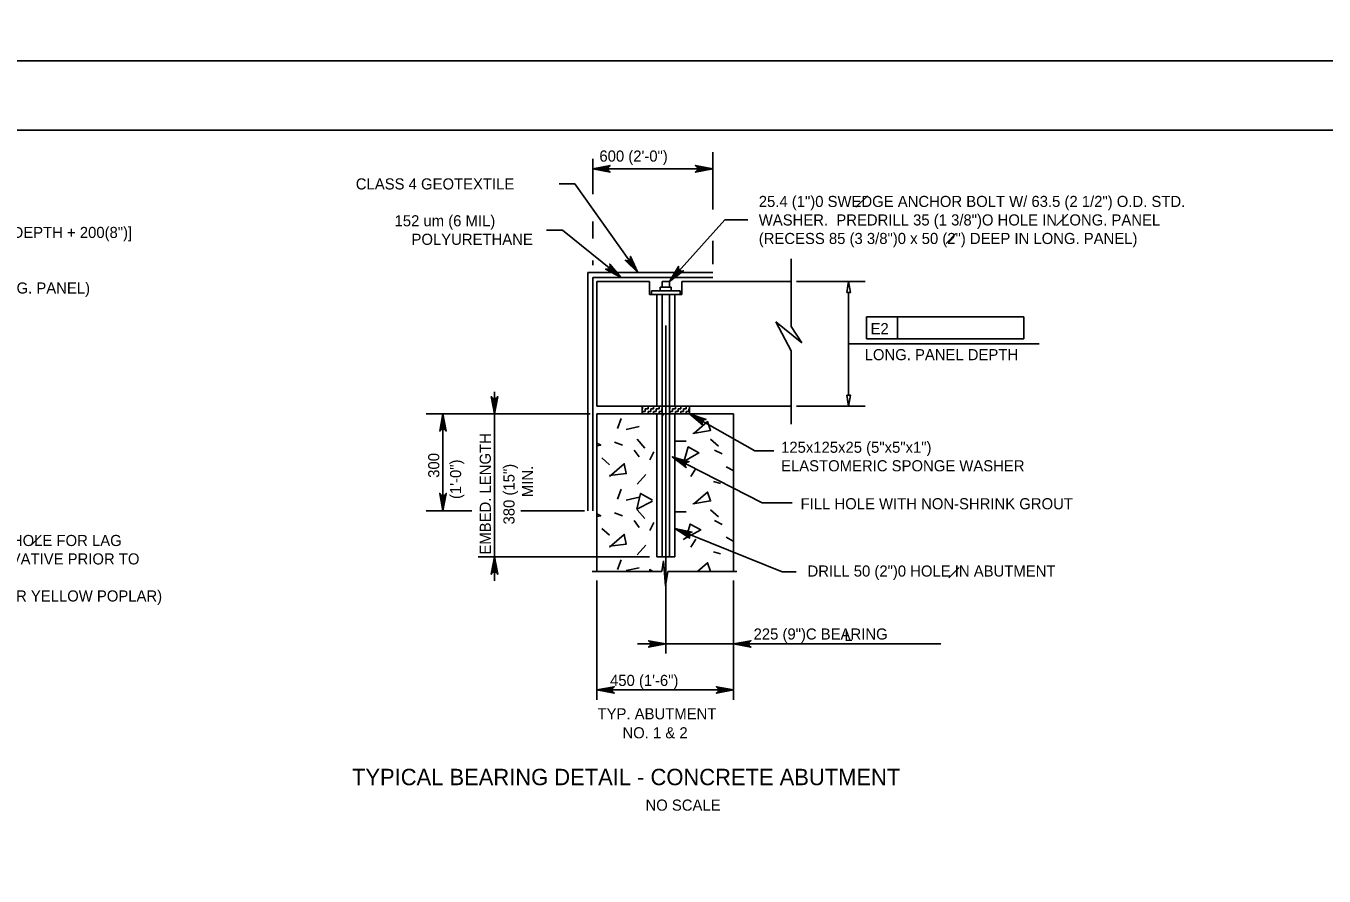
# Model space of a CAD drawing. Extents: x -8 to 75, y -110 to 0.
# Drawn here: x 45.04 to 59.07, y -74.81 to -65.62 of the extents above; entities that cross this region are included whole.
import ezdxf

# ---------------------------------------------------------------- set-up
doc = ezdxf.new("R2010")
doc.units = 0
for name, color, linetype in [('1', 7, 'Continuous'), ('2', 7, 'Continuous'), ('3', 7, 'Continuous'), ('4', 7, 'Continuous'), ('63', 7, 'Continuous')]:
    doc.layers.add(name, color=color, linetype=linetype)

msp = doc.modelspace()

# ---------------------------------------------------------------- linework, layer by layer
at = {"layer": '1'}
msp.add_lwpolyline([(35.75, -87.25), (67.25, -87.25), (67.25, -66.75), (35.75, -66.75)], close=True, dxfattribs=at)
at = {"layer": '2'}
for p, q in [((51.115, -68.286), (51.115, -70.86)), ((51.115, -68.286), (52.463, -68.286)), ((51.169, -68.34), (51.169, -70.86)), ((51.169, -68.34), (52.463, -68.34)), ((51.213, -68.384), (51.213, -69.731)), ((51.213, -68.384), (51.782, -68.384)), ((51.782, -68.526), (51.782, -68.384)), ((51.917, -68.384), (51.996, -68.384)), ((51.917, -68.384), (51.917, -68.447)), ((51.996, -68.384), (51.996, -68.447)), ((52.13, -68.526), (52.13, -68.384)), ((52.13, -68.384), (53.306, -68.384)), ((51.782, -68.526), (52.13, -68.526)), ((51.803, -68.486), (52.11, -68.486)), ((51.803, -68.526), (51.803, -68.486)), ((51.858, -69.731), (51.858, -68.526)), ((51.897, -68.486), (51.897, -68.447)), ((51.897, -68.447), (52.015, -68.447)), ((51.917, -68.526), (51.917, -71.36)), ((51.996, -68.526), (51.996, -71.36)), ((52.015, -68.486), (52.015, -68.447)), ((52.055, -69.731), (52.055, -68.526)), ((52.11, -68.526), (52.11, -68.486)), ((51.956, -68.599), (51.956, -68.599)), ((51.213, -69.731), (53.306, -69.731)), ((51.213, -69.814), (52.689, -69.814)), ((51.213, -69.814), (51.213, -71.516)), ((51.7, -69.731), (51.7, -69.814)), ((51.7, -69.76), (51.706, -69.76)), ((51.706, -69.76), (51.706, -69.731)), ((51.706, -69.79), (51.735, -69.79)), ((51.706, -69.814), (51.706, -69.79)), ((51.735, -69.76), (51.765, -69.76)), ((51.735, -69.79), (51.735, -69.76)), ((51.765, -69.76), (51.765, -69.731)), ((51.765, -69.79), (51.794, -69.79)), ((51.765, -69.814), (51.765, -69.79)), ((51.794, -69.76), (51.824, -69.76)), ((51.794, -69.79), (51.794, -69.76)), ((51.824, -69.76), (51.824, -69.731)), ((51.824, -69.79), (51.853, -69.79)), ((51.824, -69.814), (51.824, -69.79)), ((51.853, -69.76), (51.883, -69.76)), ((51.853, -69.79), (51.853, -69.76)), ((51.858, -71.36), (51.858, -69.814)), ((51.883, -69.76), (51.883, -69.731)), ((51.883, -69.79), (51.912, -69.79)), ((51.883, -69.814), (51.883, -69.79)), ((51.912, -69.76), (51.917, -69.76)), ((51.912, -69.79), (51.912, -69.76)), ((51.996, -69.76), (52.001, -69.76)), ((52.001, -69.76), (52.001, -69.731)), ((52.001, -69.79), (52.03, -69.79)), ((52.001, -69.814), (52.001, -69.79)), ((52.03, -69.76), (52.06, -69.76)), ((52.03, -69.79), (52.03, -69.76)), ((52.055, -71.36), (52.055, -69.814)), ((52.06, -69.76), (52.06, -69.731)), ((52.06, -69.79), (52.089, -69.79)), ((52.06, -69.814), (52.06, -69.79)), ((52.089, -69.76), (52.119, -69.76)), ((52.089, -69.79), (52.089, -69.76)), ((52.119, -69.76), (52.119, -69.731)), ((52.119, -69.79), (52.148, -69.79)), ((52.119, -69.814), (52.119, -69.79)), ((52.148, -69.76), (52.178, -69.76)), ((52.148, -69.79), (52.148, -69.76)), ((52.178, -69.76), (52.178, -69.731)), ((52.178, -69.79), (52.207, -69.79)), ((52.178, -69.814), (52.178, -69.79)), ((52.207, -69.76), (52.212, -69.76)), ((52.207, -69.79), (52.207, -69.76)), ((52.212, -69.731), (52.212, -69.814)), ((52.689, -69.814), (52.689, -71.516)), ((51.858, -71.36), (52.055, -71.36)), ((51.16, -71.516), (51.912, -71.516)), ((51.912, -71.516), (51.931, -71.4)), ((51.931, -71.4), (51.954, -71.67)), ((51.954, -71.67), (51.979, -71.516)), ((51.979, -71.516), (52.725, -71.516))]:
    msp.add_line(p, q, dxfattribs=at)
at = {"layer": '3'}
for p, q in [((52.463, -67.607), (52.463, -66.988)), ((51.169, -67.442), (51.169, -67.061)), ((52.463, -67.168), (51.169, -67.168)), ((50.972, -67.331), (50.803, -67.331)), ((54.011, -67.582), (54.135, -67.459)), ((51.169, -67.919), (51.169, -67.736)), ((52.593, -67.72), (52.844, -67.72)), ((56.178, -67.78), (56.302, -67.656)), ((50.839, -67.829), (50.666, -67.829)), ((54.985, -67.974), (55.092, -67.868)), ((52.464, -68.197), (52.464, -67.947)), ((51.169, -68.207), (51.169, -68.157)), ((53.311, -68.141), (53.311, -68.872)), ((53.369, -68.384), (54.112, -68.384)), ((53.932, -68.504), (53.932, -69.611)), ((51.956, -68.859), (51.956, -72.402)), ((53.144, -68.82), (53.311, -69.132)), ((53.425, -69.049), (53.144, -68.82)), ((54.125, -68.768), (55.826, -68.768)), ((54.125, -69.004), (54.125, -68.768)), ((54.46, -69.004), (54.46, -68.768)), ((55.826, -68.768), (55.826, -69.004)), ((53.311, -68.872), (53.425, -69.049)), ((55.826, -69.004), (54.125, -69.004)), ((53.311, -69.132), (53.311, -69.924)), ((53.932, -69.057), (55.992, -69.057)), ((50.105, -69.814), (50.105, -69.578)), ((50.714, -69.814), (49.369, -69.814)), ((49.549, -69.814), (49.549, -70.86)), ((51.14, -69.814), (49.928, -69.814)), ((50.105, -69.814), (50.105, -71.36)), ((51.931, -69.814), (51.921, -69.834)), ((53.369, -69.731), (54.112, -69.731)), ((51.476, -69.866), (51.434, -69.972)), ((51.667, -69.951), (51.529, -69.982)), ((51.402, -70.12), (51.487, -70.152)), ((51.646, -70.088), (51.731, -70.184)), ((52.059, -70.109), (52.175, -70.109)), ((52.44, -70.088), (52.525, -70.162)), ((51.614, -70.205), (51.667, -70.279)), ((51.826, -70.226), (51.783, -70.311)), ((52.482, -70.205), (52.567, -70.247)), ((52.917, -70.212), (53.124, -70.212)), ((51.265, -70.289), (51.349, -70.364)), ((52.228, -70.491), (52.281, -70.406)), ((52.61, -70.385), (52.684, -70.427)), ((51.741, -70.47), (51.646, -70.575)), ((52.472, -70.544), (52.546, -70.565)), ((51.476, -70.628), (51.434, -70.734)), ((51.667, -70.713), (51.529, -70.745)), ((52.998, -70.777), (53.323, -70.777)), ((49.861, -70.86), (49.369, -70.86)), ((51.079, -70.86), (50.391, -70.86)), ((51.402, -70.883), (51.487, -70.914)), ((51.614, -70.967), (51.667, -71.041)), ((51.646, -70.851), (51.731, -70.946)), ((52.059, -70.872), (52.175, -70.872)), ((52.44, -70.851), (52.525, -70.925)), ((52.482, -70.967), (52.567, -71.01)), ((51.265, -71.052), (51.349, -71.126)), ((51.826, -70.988), (51.783, -71.073)), ((45.101, -71.232), (45.209, -71.124)), ((51.741, -71.232), (51.646, -71.338)), ((52.228, -71.253), (52.281, -71.168)), ((52.61, -71.147), (52.684, -71.19)), ((51.781, -71.36), (49.928, -71.36)), ((50.105, -71.36), (50.105, -71.596)), ((52.472, -71.306), (52.546, -71.327)), ((51.476, -71.391), (51.434, -71.497)), ((51.667, -71.476), (51.529, -71.507)), ((53.215, -71.52), (53.366, -71.52)), ((55.014, -71.585), (55.127, -71.473)), ((50.105, -71.596), (50.105, -71.618)), ((51.213, -71.615), (51.213, -72.904)), ((52.689, -71.615), (52.689, -72.904)), ((52.689, -72.159), (52.689, -72.354)), ((51.956, -72.299), (51.65, -72.299)), ((51.916, -72.299), (52.925, -72.299)), ((52.925, -72.299), (54.929, -72.299)), ((52.689, -72.796), (51.213, -72.796))]:
    msp.add_line(p, q, dxfattribs=at)
for points in [[(51.169, -67.168), (51.355, -67.133), (51.341, -67.143), (51.334, -67.156), (51.331, -67.168), (51.334, -67.181), (51.341, -67.193), (51.355, -67.203), (51.169, -67.168), (51.341, -67.193), (51.334, -67.181), (51.169, -67.168), (51.331, -67.168), (51.334, -67.156), (51.169, -67.168), (51.341, -67.143)], [(52.463, -67.168), (52.277, -67.203), (52.291, -67.193), (52.299, -67.181), (52.301, -67.168), (52.299, -67.156), (52.291, -67.143), (52.277, -67.133), (52.463, -67.168), (52.291, -67.143), (52.299, -67.156), (52.463, -67.168), (52.301, -67.168), (52.299, -67.181), (52.463, -67.168), (52.291, -67.193)], [(51.655, -68.286), (50.972, -67.331)], [(51.996, -68.384), (52.593, -67.72)], [(51.473, -68.34), (50.839, -67.829)], [(51.655, -68.286), (51.519, -68.155), (51.535, -68.161), (51.549, -68.159), (51.561, -68.154), (51.57, -68.145), (51.576, -68.132), (51.575, -68.114), (51.655, -68.286), (51.576, -68.132), (51.57, -68.145), (51.655, -68.286), (51.561, -68.154), (51.549, -68.159), (51.655, -68.286), (51.535, -68.161)], [(51.473, -68.34), (51.306, -68.251), (51.324, -68.252), (51.337, -68.247), (51.347, -68.238), (51.353, -68.227), (51.355, -68.213), (51.35, -68.196), (51.473, -68.34), (51.355, -68.213), (51.353, -68.227), (51.473, -68.34), (51.347, -68.238), (51.337, -68.247), (51.473, -68.34), (51.324, -68.252)], [(51.996, -68.384), (52.094, -68.222), (52.092, -68.239), (52.096, -68.253), (52.104, -68.263), (52.115, -68.27), (52.129, -68.273), (52.146, -68.269), (51.996, -68.384), (52.129, -68.273), (52.115, -68.27), (51.996, -68.384), (52.104, -68.263), (52.096, -68.253), (51.996, -68.384), (52.092, -68.239)], [(50.105, -69.814), (50.07, -69.627), (50.08, -69.642), (50.092, -69.649), (50.105, -69.651), (50.117, -69.649), (50.13, -69.642), (50.14, -69.627), (50.105, -69.814), (50.13, -69.642), (50.117, -69.649), (50.105, -69.814), (50.105, -69.651), (50.092, -69.649), (50.105, -69.814), (50.08, -69.642)], [(49.549, -69.814), (49.584, -70), (49.574, -69.986), (49.562, -69.978), (49.549, -69.976), (49.537, -69.978), (49.524, -69.986), (49.514, -70), (49.549, -69.814), (49.524, -69.986), (49.537, -69.978), (49.549, -69.814), (49.549, -69.976), (49.562, -69.978), (49.549, -69.814), (49.574, -69.986)], [(52.212, -69.814), (52.917, -70.212)], [(52.212, -69.814), (52.392, -69.875), (52.374, -69.877), (52.362, -69.884), (52.354, -69.894), (52.349, -69.906), (52.35, -69.92), (52.357, -69.936), (52.212, -69.814), (52.35, -69.92), (52.349, -69.906), (52.212, -69.814), (52.354, -69.894), (52.362, -69.884), (52.212, -69.814), (52.374, -69.877)], [(52.249, -70.025), (52.44, -69.993), (52.408, -69.898), (52.26, -70.025)], [(51.213, -70.16), (51.254, -70.152), (51.213, -70.131)], [(52.125, -70.342), (52.315, -70.236), (52.199, -70.172), (52.156, -70.321)], [(51.349, -70.48), (51.529, -70.459), (51.508, -70.353), (51.349, -70.491)], [(52.026, -70.278), (52.998, -70.776)], [(52.026, -70.278), (52.208, -70.332), (52.19, -70.334), (52.178, -70.342), (52.17, -70.352), (52.167, -70.364), (52.167, -70.379), (52.176, -70.394), (52.026, -70.278), (52.167, -70.379), (52.167, -70.364), (52.026, -70.278), (52.17, -70.352), (52.178, -70.342), (52.026, -70.278), (52.19, -70.334)], [(49.549, -70.86), (49.514, -70.674), (49.524, -70.688), (49.537, -70.696), (49.549, -70.698), (49.562, -70.696), (49.574, -70.688), (49.584, -70.674), (49.549, -70.86), (49.574, -70.688), (49.562, -70.696), (49.549, -70.86), (49.549, -70.698), (49.537, -70.696), (49.549, -70.86), (49.524, -70.688)], [(51.811, -70.758), (51.642, -70.842), (51.684, -70.673), (51.811, -70.747)], [(52.249, -70.787), (52.44, -70.755), (52.408, -70.66), (52.26, -70.787)], [(51.213, -70.922), (51.254, -70.914), (51.213, -70.894)], [(52.055, -71.054), (53.215, -71.52)], [(52.055, -71.054), (52.241, -71.091), (52.224, -71.095), (52.212, -71.104), (52.206, -71.115), (52.203, -71.127), (52.205, -71.142), (52.215, -71.156), (52.055, -71.054), (52.205, -71.142), (52.203, -71.127), (52.055, -71.054), (52.206, -71.115), (52.212, -71.104), (52.055, -71.054), (52.224, -71.095)], [(52.144, -71.173), (52.334, -71.067), (52.218, -71.004), (52.176, -71.152)], [(51.349, -71.243), (51.529, -71.221), (51.508, -71.116), (51.349, -71.253)], [(50.105, -71.36), (50.14, -71.546), (50.13, -71.532), (50.117, -71.524), (50.105, -71.522), (50.092, -71.524), (50.08, -71.532), (50.07, -71.546), (50.105, -71.36), (50.08, -71.532), (50.092, -71.524), (50.105, -71.36), (50.105, -71.522), (50.117, -71.524), (50.105, -71.36), (50.13, -71.532)], [(51.779, -71.516), (51.783, -71.497), (51.816, -71.516)], [(52.439, -71.516), (52.408, -71.423), (52.3, -71.516)], [(51.956, -72.299), (51.77, -72.334), (51.784, -72.324), (51.792, -72.312), (51.794, -72.299), (51.792, -72.287), (51.784, -72.274), (51.77, -72.264), (51.956, -72.299), (51.784, -72.274), (51.792, -72.287), (51.956, -72.299), (51.794, -72.299), (51.792, -72.312), (51.956, -72.299), (51.784, -72.324)], [(52.689, -72.299), (52.876, -72.264), (52.861, -72.274), (52.854, -72.287), (52.852, -72.299), (52.854, -72.312), (52.861, -72.324), (52.876, -72.334), (52.689, -72.299), (52.861, -72.324), (52.854, -72.312), (52.689, -72.299), (52.852, -72.299), (52.854, -72.287), (52.689, -72.299), (52.861, -72.274)], [(51.213, -72.796), (51.399, -72.762), (51.385, -72.772), (51.377, -72.784), (51.375, -72.796), (51.377, -72.809), (51.385, -72.822), (51.399, -72.831), (51.213, -72.796), (51.385, -72.822), (51.377, -72.809), (51.213, -72.796), (51.375, -72.796), (51.377, -72.784), (51.213, -72.796), (51.385, -72.772)], [(52.689, -72.796), (52.503, -72.831), (52.517, -72.822), (52.525, -72.809), (52.527, -72.796), (52.525, -72.784), (52.517, -72.772), (52.503, -72.762), (52.689, -72.796), (52.517, -72.772), (52.525, -72.784), (52.689, -72.796), (52.527, -72.796), (52.525, -72.809), (52.689, -72.796), (52.517, -72.822)]]:
    msp.add_lwpolyline(points, dxfattribs=at)
for points in [[(51.289, -67.148), (51.289, -67.188), (51.169, -67.168)], [(52.343, -67.148), (52.343, -67.188), (52.463, -67.168)], [(51.473, -68.34), (51.386, -68.257), (51.373, -68.273)], [(51.655, -68.286), (51.594, -68.183), (51.578, -68.194)], [(51.996, -68.384), (52.083, -68.302), (52.069, -68.288)], [(53.912, -68.504), (53.952, -68.504), (53.932, -68.384)], [(50.085, -69.696), (50.124, -69.696), (50.105, -69.814)], [(53.912, -69.611), (53.952, -69.611), (53.932, -69.731)], [(49.529, -69.934), (49.569, -69.934), (49.549, -69.814)], [(49.529, -70.74), (49.569, -70.74), (49.549, -70.86)], [(50.085, -71.478), (50.124, -71.478), (50.105, -71.36)], [(51.798, -72.28), (51.798, -72.319), (51.916, -72.299)], [(52.807, -72.28), (52.807, -72.319), (52.689, -72.299)], [(51.331, -72.777), (51.331, -72.816), (51.213, -72.796)], [(52.571, -72.777), (52.571, -72.816), (52.689, -72.796)]]:
    msp.add_lwpolyline(points, close=True, dxfattribs=at)
at = {"layer": '63'}
for points in [[(34, -66), (68, -66), (68, -44), (34, -44)], [(34, -88), (68, -88), (68, -66), (34, -66)]]:
    msp.add_lwpolyline(points, close=True, dxfattribs=at)

# ---------------------------------------------------------------- texts
at = {"layer": '2'}
msp.add_text('TYPICAL BEARING DETAIL - CONCRETE ABUTMENT', height=0.17717, dxfattribs=at).set_placement((48.566, -73.825))
at = {"layer": '3'}
for s, p in [('600 (2\'-0")', (51.239, -67.09)), ('CLASS 4 GEOTEXTILE', (48.607, -67.391)), ('25.4 (1")0 SWEDGE ANCHOR BOLT W/ 63.5 (2 1/2") O.D. STD.', (52.961, -67.58)), ('152 um (6 MIL)', (49.026, -67.789)), ('WASHER.  PREDRILL 35 (1 3/8")O HOLE IN LONG. PANEL', (52.961, -67.78)), ('19.1(3/4") 0 LAG SCREW [LENGTH = PANEL DEPTH + 200(8")]', (41.564, -67.915)), ('POLYURETHANE', (49.209, -67.989)), ('(RECESS 85 (3 3/8")0 x 50 (2") DEEP IN LONG. PANEL)', (52.961, -67.98)), ('(RECESS 85 (3 3/8") O x 25 (1") DEEP IN LONG. PANEL)', (41.564, -68.515)), ('E2', (54.169, -68.954)), ('LONG. PANEL DEPTH', (54.105, -69.235)), ('FILL HOLE WITH NON-SHRINK GROUT', (53.413, -70.845)), ('FIELD DRILL 14.3 (9/16") 0 PILOT HOLE FOR LAG', (42.373, -71.242)), ('SCREW AND FILL WITH PRESERVATIVE PRIOR TO', (42.373, -71.441)), ('DRILL 50 (2")0 HOLE IN ABUTMENT', (53.488, -71.572)), ('(USE 12.7 (1/2") 0 PILOT HOLE FOR YELLOW POPLAR)', (42.373, -71.841)), ('225 (9")C BEARING', (52.905, -72.252)), ('L', (53.885, -72.268)), ('450 (1\'-6")', (51.354, -72.753)), ('TYP. ABUTMENT', (51.219, -73.114)), ('NO. 1 & 2', (51.488, -73.319)), ('NO SCALE', (51.737, -74.1))]:
    msp.add_text(s, height=0.12, dxfattribs=at).set_placement(p)
for s, p in [('EMBED. LENGTH', (50.066, -71.334)), ('300', (49.509, -70.505)), ('(1\'-0")', (49.745, -70.734)), ('380 (15")', (50.322, -71.009)), ('MIN.', (50.522, -70.714))]:
    msp.add_text(s, height=0.12, rotation=90, dxfattribs=at).set_placement(p)
at = {"layer": '4'}
for s, p in [('125x125x25 (5"x5"x1")', (53.202, -70.235)), ('ELASTOMERIC SPONGE WASHER', (53.202, -70.435))]:
    msp.add_text(s, height=0.12, dxfattribs=at).set_placement(p)

doc.saveas('drawing.dxf')
